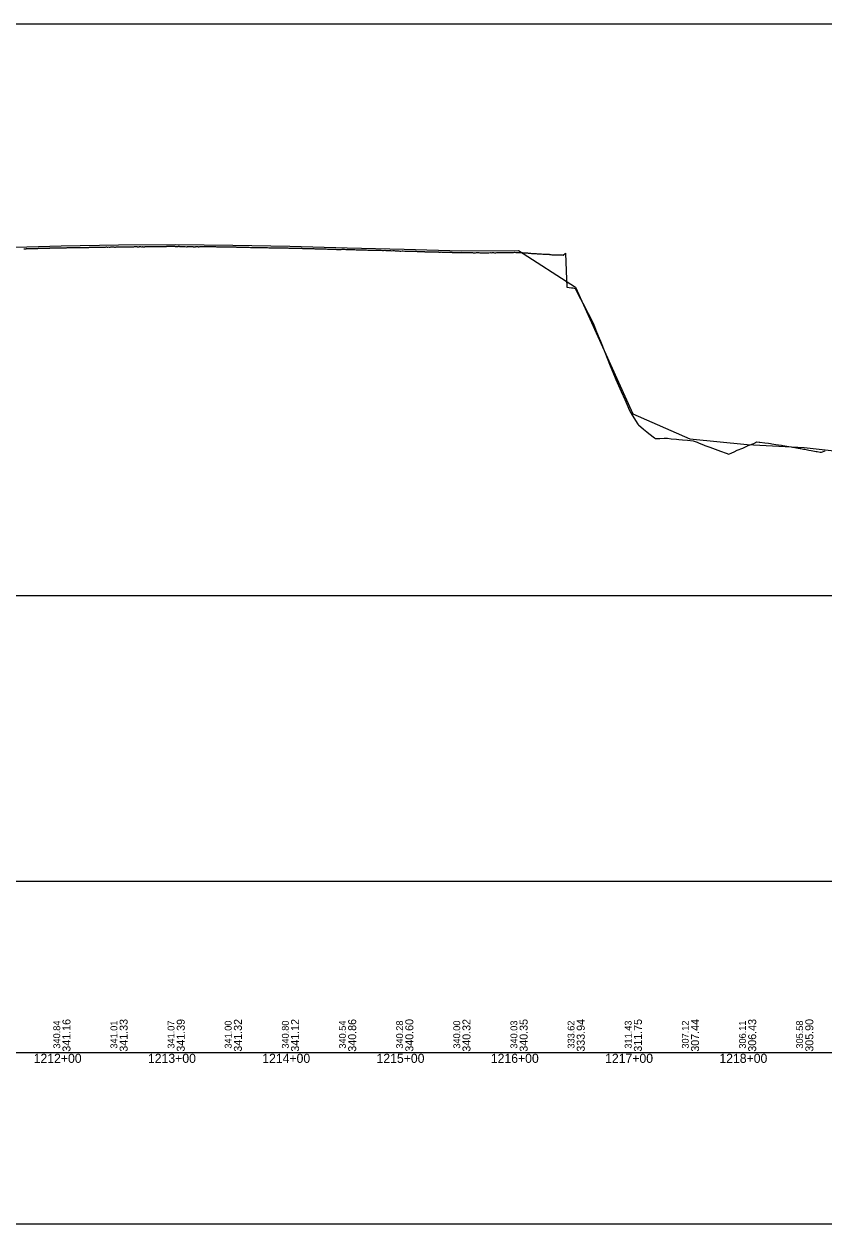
# Model space of a CAD drawing. Extents: x 2898 to 49495, y -15038 to -13538.
# Drawn here: x 10521 to 11221, y -15038 to -13988 of the extents above; entities that cross this region are included whole.
import ezdxf

# ---------------------------------------------------------------- set-up
doc = ezdxf.new("R2010")
doc.units = 0
for name, color, linetype in [('RD_DDB_Profile_EX', 7, 'Continuous'), ('RD_DDB_Profile_PR', 7, 'Continuous'), ('RD_DDB_StaTX', 7, 'Continuous'), ('RD_DDB_StripGrade', 7, 'Continuous'), ('RD_GPK_Profile_Cell', 7, 'Continuous'), ('RD_SHT_ShtClip', 7, 'Continuous')]:
    doc.layers.add(name, color=color, linetype=linetype)

msp = doc.modelspace()

# ---------------------------------------------------------------- linework, layer by layer
at = {"layer": 'RD_DDB_Profile_EX'}
for points in [[(10520.7, -14185.1), (10521.3, -14185.1), (10521.6, -14185.1), (10522.3, -14185.1), (10522.6, -14185.1), (10523, -14185), (10523.3, -14185), (10523.7, -14185), (10524.3, -14185), (10524.6, -14185), (10525.3, -14184.9), (10525.7, -14185), (10526.3, -14185), (10526.7, -14185), (10527.3, -14185), (10527.8, -14184.9), (10528.3, -14184.9), (10528.7, -14184.9), (10529.3, -14184.9), (10529.7, -14184.8), (10530.3, -14184.8), (10530.7, -14184.8), (10531.3, -14184.8), (10531.7, -14184.8), (10532.3, -14184.8), (10532.7, -14184.8), (10533.3, -14184.7), (10533.7, -14184.7), (10534.3, -14184.7), (10534.7, -14184.7), (10535.3, -14184.6), (10535.7, -14184.7), (10536.3, -14184.7), (10536.7, -14184.7), (10537.8, -14184.6), (10538.4, -14184.5), (10538.7, -14184.5), (10539.4, -14184.5), (10539.7, -14184.5), (10540.4, -14184.5), (10540.8, -14184.5), (10541.4, -14184.5), (10541.7, -14184.5), (10542.4, -14184.5), (10542.7, -14184.6), (10543.4, -14184.5)], [(10543.4, -14184.5), (10543.7, -14184.4), (10544.4, -14184.4), (10544.8, -14184.4), (10545.5, -14184.4), (10545.8, -14184.4), (10546.5, -14184.4), (10547.1, -14184.4), (10547.5, -14184.4), (10547.8, -14184.3), (10548.5, -14184.3), (10548.8, -14184.3), (10549.5, -14184.3), (10549.8, -14184.3), (10550.5, -14184.3), (10550.8, -14184.4), (10551.5, -14184.4), (10551.9, -14184.3), (10552.5, -14184.3), (10552.8, -14184.3), (10553.5, -14184.2), (10553.8, -14184.2), (10554.5, -14184.2), (10554.8, -14184.2), (10555.5, -14184.2), (10555.8, -14184.2), (10556.8, -14184.2), (10557.5, -14184.2), (10557.8, -14184.2), (10558.5, -14184.1), (10558.8, -14184.1), (10559.5, -14184.1), (10559.8, -14184.1), (10560.5, -14184.1), (10560.8, -14184.1), (10561.8, -14184.1), (10562.5, -14184.1), (10562.8, -14184.1), (10563.5, -14184.1), (10563.8, -14184.1), (10564.5, -14184), (10564.8, -14184), (10565.5, -14184), (10565.8, -14184), (10566.5, -14184), (10566.8, -14184), (10567.5, -14184), (10567.8, -14184), (10568.5, -14184), (10568.8, -14183.9), (10569.5, -14183.9), (10569.8, -14183.9), (10570.5, -14183.9), (10570.8, -14184), (10571.5, -14184), (10571.8, -14183.9), (10572.6, -14183.9), (10573, -14183.9), (10573.6, -14183.9), (10574, -14183.9), (10574.6, -14183.9), (10575, -14183.9), (10575.6, -14183.9), (10576, -14183.9), (10576.6, -14183.9), (10577, -14183.9), (10577.6, -14183.9), (10578, -14183.8), (10578.6, -14183.8), (10579, -14183.8), (10579.6, -14183.8), (10580, -14183.8), (10581, -14183.8), (10581.6, -14183.7), (10582, -14183.7), (10582.6, -14183.7), (10583, -14183.7), (10583.6, -14183.7), (10584, -14183.7), (10584.6, -14183.7), (10585, -14183.7), (10585.6, -14183.7), (10586, -14183.8), (10586.6, -14183.7), (10587, -14183.7), (10587.6, -14183.7), (10588, -14183.7), (10588.6, -14183.7), (10589, -14183.7), (10589.6, -14183.7), (10590, -14183.6), (10590.6, -14183.6), (10591, -14183.6), (10591.6, -14183.6), (10592, -14183.6), (10592.6, -14183.5), (10593, -14183.5), (10593.6, -14183.6), (10594, -14183.6), (10594.6, -14183.5), (10595.2, -14183.6)], [(10595.2, -14183.6), (10595.6, -14183.6), (10596, -14183.6), (10596.6, -14183.5), (10597, -14183.5), (10597.6, -14183.5), (10598, -14183.5), (10598.8, -14183.5), (10599.4, -14183.5), (10599.8, -14183.6), (10600.1, -14183.6), (10600.4, -14183.6), (10600.8, -14183.6), (10601.4, -14183.5), (10601.8, -14183.5), (10602.5, -14183.4), (10602.8, -14183.4), (10603.5, -14183.4), (10603.8, -14183.4), (10604.5, -14183.4), (10604.9, -14183.4), (10605.5, -14183.4), (10605.8, -14183.4), (10606.5, -14183.4), (10606.8, -14183.4), (10607.5, -14183.4), (10607.8, -14183.4), (10608.5, -14183.4), (10608.8, -14183.3), (10609.8, -14183.3), (10610.5, -14183.3), (10610.8, -14183.4), (10611.5, -14183.4), (10611.8, -14183.4), (10612.5, -14183.4), (10612.8, -14183.4), (10613.5, -14183.4), (10613.8, -14183.4), (10614.5, -14183.4), (10614.8, -14183.4), (10615.5, -14183.3), (10615.8, -14183.3), (10616.5, -14183.3), (10616.8, -14183.3), (10617.5, -14183.2), (10617.8, -14183.2), (10618.5, -14183.2), (10618.8, -14183.2), (10619.5, -14183.2), (10619.8, -14183.3), (10620.5, -14183.3), (10620.8, -14183.3), (10621.5, -14183.3), (10621.8, -14183.2), (10622.5, -14183.2), (10622.8, -14183.2), (10623.5, -14183.3), (10623.8, -14183.3), (10624.1, -14183.3), (10624.5, -14183.2), (10624.8, -14183.3), (10625.5, -14183.3), (10625.8, -14183.3), (10626.5, -14183.3), (10626.9, -14183.2), (10627.6, -14183.2), (10627.9, -14183.2), (10628.6, -14183.2), (10629, -14183.2), (10629.6, -14183.2), (10629.9, -14183.2), (10630.6, -14183.2), (10630.9, -14183.2), (10631.6, -14183.2), (10631.9, -14183.2), (10632.6, -14183.2), (10632.9, -14183.2), (10633.9, -14183.1), (10634.6, -14183.1), (10634.9, -14183.1), (10635.5, -14183.1), (10635.8, -14183.1), (10636.5, -14183.1), (10636.8, -14183.2), (10637.5, -14183.1), (10637.8, -14183.1), (10638.8, -14183.1), (10639.5, -14183.2), (10639.8, -14183.1), (10640.5, -14183.1), (10640.8, -14183.1), (10641.5, -14183.1), (10641.8, -14183.2), (10642.5, -14183.1), (10642.8, -14183.1), (10643.5, -14183.1), (10643.8, -14183.1), (10644.5, -14183.1), (10644.8, -14183.1), (10645.5, -14183.1), (10645.8, -14183)], [(10645.8, -14183), (10646.5, -14183), (10646.8, -14183), (10647.5, -14183), (10647.8, -14183), (10648.2, -14183), (10648.5, -14183), (10648.8, -14183), (10649.5, -14183), (10649.8, -14183), (10650.5, -14183), (10650.8, -14183), (10651.5, -14183), (10651.8, -14183), (10652.5, -14183), (10653, -14183.1), (10653.8, -14183.1), (10654.5, -14183.1), (10654.8, -14183.1), (10655.5, -14183.1), (10655.8, -14183), (10656.5, -14183), (10656.8, -14183.1), (10657.5, -14183.1), (10657.8, -14183.1), (10658.5, -14183.2), (10658.8, -14183.2), (10659.5, -14183.2), (10659.8, -14183.2), (10660.5, -14183.2), (10660.8, -14183.2), (10661.5, -14183.2), (10661.8, -14183.2), (10662.8, -14183.3), (10663.5, -14183.3), (10663.8, -14183.2), (10664.5, -14183.2), (10664.8, -14183.1), (10665.5, -14183.1), (10665.8, -14183.1), (10666.5, -14183.1), (10666.8, -14183.1), (10667.5, -14183.1), (10667.8, -14183.1), (10668.5, -14183.1), (10668.8, -14183.3), (10669.5, -14183.3), (10670, -14183.3), (10670.7, -14183.3), (10671, -14183.1), (10671.7, -14183.1), (10672, -14183.1), (10672.3, -14183.1), (10672.7, -14183.1), (10673, -14183.3), (10673.7, -14183.3), (10674, -14183.3), (10674.7, -14183.2), (10675, -14183.2), (10675.7, -14183.2), (10676, -14183.2), (10676.7, -14183.2), (10677.1, -14183.1), (10677.7, -14183.1), (10678, -14183.2), (10678.7, -14183.2), (10679, -14183.2), (10679.7, -14183.1), (10680, -14183.1), (10680.7, -14183.2), (10681, -14183.1), (10681.9, -14183.1), (10682.2, -14183.1), (10683.2, -14183.2), (10683.9, -14183.2), (10684.2, -14183.2), (10685.2, -14183.2), (10686.2, -14183.2), (10687.2, -14183.2), (10688.2, -14183.2), (10689.2, -14183.3), (10690.2, -14183.3), (10691.2, -14183.3), (10691.6, -14183.3), (10692.2, -14183.3), (10693.2, -14183.3), (10694.2, -14183.3), (10695.2, -14183.3), (10696.4, -14183.3), (10697.2, -14183.4), (10698.2, -14183.4), (10699.2, -14183.4), (10700.2, -14183.3), (10701.2, -14183.4), (10702.2, -14183.4), (10703.2, -14183.5), (10703.9, -14183.5), (10704.7, -14183.5), (10705.7, -14183.5), (10706, -14183.5), (10706.7, -14183.6)], [(10706.7, -14183.6), (10707.7, -14183.6), (10708.8, -14183.6), (10709.8, -14183.6), (10710.8, -14183.7), (10711.8, -14183.7), (10712.8, -14183.7), (10713.8, -14183.8), (10714.8, -14183.7), (10715.8, -14183.8), (10716.8, -14183.7), (10717.8, -14183.8), (10718.8, -14183.9), (10719.8, -14183.9), (10720.8, -14183.9), (10721.8, -14183.9), (10722.8, -14183.9), (10723.8, -14183.9), (10724.8, -14184), (10725.8, -14184), (10726.8, -14184), (10727.8, -14184), (10728.8, -14184), (10730.1, -14184.1), (10730.8, -14184.1), (10731.8, -14184.1), (10732.8, -14184.1), (10733.8, -14184.1), (10734.9, -14184.2), (10735.8, -14184.2), (10736.8, -14184.2), (10737.8, -14184.2), (10738.8, -14184.2), (10739.7, -14184.2), (10740.5, -14184.2), (10741.5, -14184.3), (10742.5, -14184.3), (10743.5, -14184.3), (10744.5, -14184.3), (10745.5, -14184.3), (10746.5, -14184.4), (10747.5, -14184.4), (10748.5, -14184.4), (10749.5, -14184.3), (10750.5, -14184.4), (10751.5, -14184.4), (10752.5, -14184.5), (10753.5, -14184.5), (10754.5, -14184.5), (10755.5, -14184.6), (10756.5, -14184.6), (10757.5, -14184.6), (10758.5, -14184.6), (10759.5, -14184.6), (10760.5, -14184.7), (10761.5, -14184.7), (10762.5, -14184.7), (10763.8, -14184.7), (10764.5, -14184.8), (10765.5, -14184.8), (10766.5, -14184.9), (10767.5, -14184.9), (10768.6, -14184.9), (10769.5, -14184.9), (10770.5, -14185), (10771.5, -14185), (10772.1, -14185), (10773.4, -14185), (10774.2, -14185), (10775.2, -14185.1), (10776.2, -14185.1), (10777.2, -14185.1), (10778.2, -14185.1), (10779.2, -14185.1), (10780.2, -14185.1), (10781.2, -14185.2), (10782.2, -14185.3), (10783.2, -14185.3), (10784.2, -14185.3), (10785.2, -14185.3), (10786.2, -14185.4), (10787.2, -14185.4), (10788.2, -14185.4), (10789.2, -14185.4), (10790.2, -14185.5), (10791.2, -14185.5), (10792.2, -14185.5), (10792.7, -14185.5), (10793.2, -14185.6), (10794.2, -14185.7), (10795.2, -14185.7), (10796.2, -14185.7), (10797.5, -14185.7), (10798.2, -14185.7), (10799.2, -14185.6), (10800.2, -14185.6), (10801.2, -14185.6), (10802.3, -14185.7), (10803.2, -14185.7), (10804.2, -14185.8), (10805.2, -14185.8)], [(10805.2, -14185.8), (10806.2, -14185.8), (10807.2, -14185.9), (10808.2, -14185.9), (10809.3, -14185.9), (10810.3, -14185.9), (10811.3, -14186), (10812.3, -14186), (10813.3, -14186), (10814.3, -14186), (10815.3, -14186), (10816.4, -14186.1), (10816.8, -14186.1), (10817.4, -14186.1), (10818.4, -14186.1), (10819.4, -14186.1), (10820.4, -14186.2), (10821.6, -14186.3), (10822.4, -14186.3), (10823.4, -14186.3), (10824.4, -14186.3), (10825.4, -14186.3), (10826.4, -14186.3), (10827.4, -14186.3), (10828.4, -14186.3), (10829.4, -14186.4), (10830.4, -14186.4), (10831.4, -14186.5), (10832.4, -14186.5), (10833.4, -14186.5), (10834.4, -14186.6), (10835.4, -14186.6), (10836.4, -14186.5), (10837.4, -14186.6), (10838.4, -14186.6), (10839.4, -14186.6), (10840.4, -14186.6), (10840.8, -14186.7), (10841.4, -14186.7), (10842.4, -14186.8), (10843.6, -14186.7), (10844.6, -14186.7), (10845.6, -14186.9), (10846.6, -14186.9), (10847.6, -14186.9), (10848.6, -14186.8), (10849.6, -14187.1), (10850.6, -14187.1), (10851.6, -14187), (10852.6, -14187), (10854, -14187.1), (10855.3, -14187.1), (10856, -14187.1), (10857, -14187.2), (10858, -14187.3), (10859, -14187.3), (10860.1, -14187.3), (10861, -14187.3), (10862, -14187.3), (10862.9, -14187.3), (10863.9, -14187.3), (10864.9, -14187.4), (10865.9, -14187.4), (10866.9, -14187.4), (10867.6, -14187.4), (10867.9, -14187.4), (10868.3, -14187.4), (10868.6, -14187.5), (10869.3, -14187.5), (10869.7, -14187.6), (10870.3, -14187.6), (10870.6, -14187.6), (10871.3, -14187.6), (10871.6, -14187.7), (10872.3, -14187.8), (10872.6, -14187.7), (10873.3, -14187.8), (10873.6, -14187.7), (10874.6, -14187.7), (10875.3, -14187.7), (10875.6, -14187.7), (10876.3, -14187.7), (10876.6, -14187.7), (10877.3, -14187.7), (10877.6, -14187.8), (10878.3, -14187.9), (10878.6, -14187.9), (10879.6, -14187.8), (10880.3, -14187.8), (10880.6, -14187.9), (10881.3, -14187.9), (10881.6, -14187.8), (10882.3, -14187.9), (10882.6, -14187.9), (10883.3, -14187.9), (10883.6, -14188), (10884.3, -14188), (10884.6, -14188), (10885.3, -14188), (10885.6, -14187.9), (10886.3, -14188)], [(10886.3, -14188), (10886.6, -14188), (10887.3, -14188), (10887.6, -14188.1), (10888.3, -14188.1), (10888.6, -14188.1), (10889.3, -14188.1), (10889.6, -14188), (10890.3, -14188), (10890.6, -14188), (10891.3, -14188.1), (10891.6, -14188), (10892.3, -14188), (10892.6, -14188.1), (10893.5, -14188.1), (10893.8, -14188.1), (10894.2, -14188.1), (10894.5, -14188.2), (10895.2, -14188.2), (10895.5, -14188.3), (10896.2, -14188.3), (10896.5, -14188.3), (10897.2, -14188.3), (10897.5, -14188.3), (10898.2, -14188.3), (10898.6, -14188.3), (10899.4, -14188.4), (10899.7, -14188.4), (10900.4, -14188.4), (10900.7, -14188.4), (10901.4, -14188.4), (10901.7, -14188.4), (10902.7, -14188.4), (10903.7, -14188.4), (10904.7, -14188.5), (10905.7, -14188.5), (10906.7, -14188.5), (10907.7, -14188.5), (10908.7, -14188.4), (10909.7, -14188.4), (10910.7, -14188.5), (10911.7, -14188.5), (10912.7, -14188.5), (10913.1, -14188.5), (10913.7, -14188.6), (10914.7, -14188.6), (10915.7, -14188.6), (10916.7, -14188.5), (10917.9, -14188.5), (10918.7, -14188.5), (10919.6, -14188.6), (10920.6, -14188.6), (10921.6, -14188.6), (10922.7, -14188.6), (10923.6, -14188.6), (10924.6, -14188.7), (10925.6, -14188.7), (10926.6, -14188.6), (10927.6, -14188.6), (10928.6, -14188.5), (10929.5, -14188.6), (10930.5, -14188.5), (10931.5, -14188.5), (10932.5, -14188.6), (10933.5, -14188.7), (10934.5, -14188.5), (10935.5, -14188.5), (10936.5, -14188.4), (10937.5, -14188.4), (10938.3, -14188.4), (10938.8, -14188.4), (10939.5, -14188.4), (10940.5, -14188.4), (10941.5, -14188.4), (10942, -14188.4), (10942.5, -14188.4), (10943.5, -14188.3), (10944.5, -14188.3), (10946, -14188.4), (10947, -14188.3), (10948, -14188.4), (10949, -14188.4), (10950, -14188.2), (10951, -14188.3), (10952, -14188.4), (10953, -14188.3), (10954, -14188.3), (10955, -14188.5), (10956, -14188.5), (10957, -14188.5), (10958, -14188.6), (10959, -14188.6), (10960, -14188.6), (10961.3, -14188.8), (10962, -14188.9), (10963, -14189.1), (10963.9, -14189.1), (10964.9, -14189.3), (10966.1, -14189.3), (10966.9, -14189.3), (10967.9, -14189.3)], [(10967.9, -14189.3), (10968.9, -14189.4), (10969.9, -14189.5), (10970.9, -14189.5), (10971.9, -14189.7), (10972.9, -14189.7), (10973.6, -14189.7), (10974.6, -14189.8), (10975.8, -14189.9), (10976.6, -14189.9), (10977.6, -14190), (10978.6, -14190), (10979.6, -14189.9), (10980.3, -14189.9), (10980.6, -14190.1), (10981.6, -14190.2), (10982.6, -14190.3), (10983.6, -14190.3), (10984.6, -14190.3), (10985.6, -14190.3), (10986.3, -14190.5), (10987, -14190.4), (10987.6, -14190.3), (10988.6, -14190.4), (10989.6, -14190.4), (10990.3, -14190.4), (10991, -14190.5), (10991.7, -14190.5), (10992.6, -14190.6), (10994.6, -14189.1), (10995.1, -14204.3), (10995.6, -14218.7), (10999.9, -14219.2), (11000.9, -14219.3), (11003.1, -14219.8), (11005, -14223.8), (11005.5, -14225.2), (11009.6, -14232.8), (11014.4, -14241.9), (11017.9, -14248.4), (11019.2, -14251.7), (11021.8, -14257.9), (11024.1, -14263.4), (11025.1, -14266), (11028.9, -14275.5), (11033.7, -14287.5), (11037.4, -14296.7), (11038.6, -14299.6), (11043.4, -14310.1), (11046.6, -14317.1), (11048.2, -14321.1), (11050.5, -14326.7), (11053, -14330.8), (11057.9, -14338.5), (11058.3, -14339.2), (11062.7, -14342.9), (11065.8, -14345.4), (11067.5, -14346.8), (11072.4, -14350.7), (11073, -14351.2), (11077.2, -14351.1), (11080.8, -14350.9), (11082.1, -14350.9), (11083.8, -14351), (11086.9, -14351.3), (11091.7, -14351.7), (11093.8, -14351.9), (11096.8, -14352.3), (11101.3, -14352.7), (11106.2, -14353.2), (11107.2, -14353.4), (11109.7, -14354.3), (11111, -14354.9), (11115.8, -14356.9), (11116.4, -14357.2), (11120.7, -14358.7), (11125.5, -14360.5), (11130.3, -14362.3), (11135.2, -14364.1), (11137.4, -14364.9), (11140, -14363.7), (11142, -14362.7), (11144.8, -14361.5), (11149.7, -14359.5), (11154.5, -14357.4), (11159.3, -14355.4), (11162.1, -14354.2), (11164.1, -14354.4), (11164.6, -14354.5), (11169, -14355), (11172.2, -14355.3), (11173.8, -14355.6), (11175.2, -14355.8), (11178.6, -14356.3), (11183.5, -14357.1), (11184.6, -14357.3), (11188.3, -14357.9), (11192.1, -14358.4), (11193.1, -14358.6), (11193.9, -14358.8), (11195.1, -14359)], [(11195.1, -14359), (11196.6, -14359.3), (11197, -14359.3), (11198, -14359.5), (11199.9, -14359.9), (11200.6, -14360), (11202.8, -14360.4), (11203.7, -14360.6), (11205.1, -14360.9), (11207.6, -14361.3), (11209.6, -14361.7), (11211, -14361.9), (11212.4, -14362.2), (11214, -14362.5), (11214.7, -14362.6), (11217.3, -14363.1), (11217.9, -14363.2), (11218.6, -14363), (11221.7, -14362)]]:
    msp.add_lwpolyline(points, dxfattribs=at)
at = {"layer": 'RD_DDB_Profile_PR'}
msp.add_lwpolyline([(10503.4, -14184), (10553.4, -14182.6), (10603.4, -14181.8), (10653.4, -14181.5), (10703.4, -14181.9), (10753.4, -14182.9), (10803.4, -14184.2), (10853.4, -14185.5), (10903.4, -14186.8), (10953.4, -14186.7), (11003.4, -14218.8), (11053.4, -14329.7), (11103.4, -14351.3), (11153.4, -14356.3), (11203.4, -14359), (11253.4, -14364.5)], dxfattribs=at)
at = {"layer": 'RD_GPK_Profile_Cell'}
msp.add_line((2976.1, -14888.5), (48721.1, -14888.5), dxfattribs=at)
at = {"layer": 'RD_SHT_ShtClip'}
for points in [[(11976.2, -14488.5), (11976.2, -13988.5), (11976.2, -13988.5), (10476.4, -13988.5), (10476.4, -14488.5)], [(10456.4, -14738.5), (11996.1, -14738.5), (11996.1, -15038.5), (10456.4, -15038.5)]]:
    msp.add_lwpolyline(points, close=True, dxfattribs=at)

# ---------------------------------------------------------------- texts
at = {"layer": 'RD_DDB_StaTX'}
for s, p in [('1212+00', (10529.2, -14897.5)), ('1213+00', (10629.2, -14897.5)), ('1214+00', (10729.2, -14897.5)), ('1215+00', (10829.2, -14897.5)), ('1216+00', (10929.2, -14897.5)), ('1217+00', (11029.2, -14897.5)), ('1218+00', (11129.2, -14897.5))]:
    msp.add_text(s, height=8, dxfattribs=at).set_placement(p)
at = {"layer": 'RD_DDB_StripGrade'}
for s, height, p in [('340.84', 6, (10552.4, -14885)), ('341.16', 7, (10561.4, -14887.7)), ('341.01', 6, (10602.4, -14885)), ('341.33', 7, (10611.4, -14887.7)), ('341.07', 6, (10652.4, -14885)), ('341.39', 7, (10661.4, -14887.7)), ('341.00', 6, (10702.4, -14885)), ('341.32', 7, (10711.4, -14887.7)), ('340.80', 6, (10752.4, -14885)), ('341.12', 7, (10761.4, -14887.7)), ('340.54', 6, (10802.4, -14885)), ('340.86', 7, (10811.4, -14887.7)), ('340.28', 6, (10852.4, -14885)), ('340.60', 7, (10861.4, -14887.7)), ('340.00', 6, (10902.4, -14885)), ('340.32', 7, (10911.4, -14887.7)), ('340.03', 6, (10952.4, -14885)), ('340.35', 7, (10961.4, -14887.7)), ('333.62', 6, (11002.4, -14885)), ('333.94', 7, (11011.4, -14887.7)), ('311.43', 6, (11052.4, -14885)), ('311.75', 7, (11061.4, -14887.7)), ('307.12', 6, (11102.4, -14885)), ('307.44', 7, (11111.4, -14887.7)), ('306.11', 6, (11152.4, -14885)), ('306.43', 7, (11161.4, -14887.7)), ('305.58', 6, (11202.4, -14885)), ('305.90', 7, (11211.4, -14887.7))]:
    msp.add_text(s, height=height, rotation=90, dxfattribs=at).set_placement(p)

doc.saveas('drawing.dxf')
